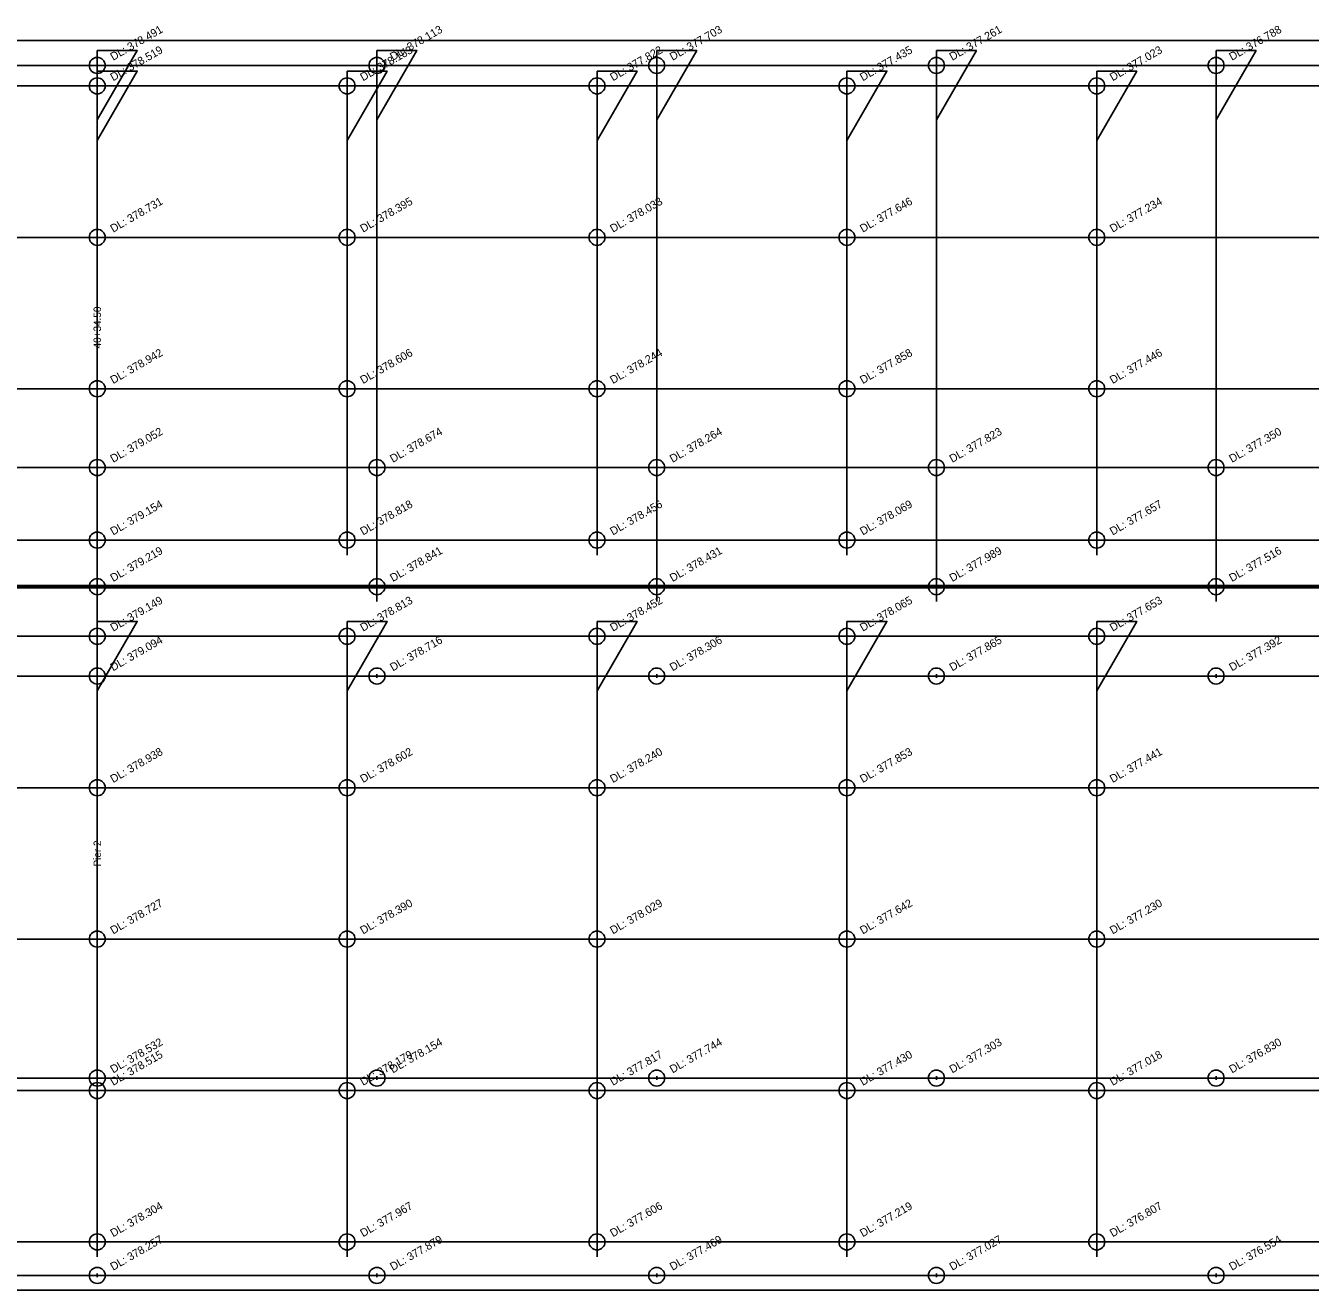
# Model space of a CAD drawing. Extents: x 100440 to 101111, y 50226 to 50315.
# Drawn here: x 100860.7 to 100946.9, y 50225.9 to 50310.8 of the extents above; entities that cross this region are included whole.
import ezdxf

# ---------------------------------------------------------------- set-up
doc = ezdxf.new("R2010")
doc.units = 0
for name, color, linetype in [('Level 1', 7, 'Continuous'), ('Level 10', 7, 'Continuous'), ('Level 21', 7, 'Continuous'), ('Level 23', 7, 'Continuous')]:
    doc.layers.add(name, color=color, linetype=linetype)

msp = doc.modelspace()

# ---------------------------------------------------------------- linework, layer by layer
at = {"layer": 'Level 1'}
for p, q in [((100559.504, 50306.768), (101034.504, 50306.768)), ((100559.504, 50296.601), (101034.504, 50296.601)), ((100865.504, 50288.143), (100865.504, 50258.143)), ((100865.504, 50288.143), (100865.504, 50258.143)), ((100559.504, 50286.435), (101034.504, 50286.435)), ((100559.504, 50276.268), (101034.504, 50276.268)), ((100559.504, 50269.81), (101034.504, 50269.81)), ((100559.504, 50259.643), (101034.504, 50259.643)), ((100559.504, 50249.476), (101034.504, 50249.476)), ((100559.504, 50239.31), (101034.504, 50239.31)), ((100559.504, 50229.143), (101034.504, 50229.143))]:
    msp.add_line(p, q, dxfattribs=at)
at = {"layer": 'Level 10'}
for p, q in [((100865.504, 50273.268), (100865.504, 50273.018)), ((100865.504, 50273.268), (100865.504, 50273.018)), ((100884.282, 50273.268), (100884.282, 50273.018)), ((100903.06, 50273.268), (100903.06, 50273.018)), ((100921.837, 50273.268), (100921.837, 50273.018)), ((100940.615, 50273.268), (100940.615, 50273.018)), ((100865.504, 50267.268), (100865.504, 50267.018)), ((100865.504, 50267.268), (100865.504, 50267.018)), ((100884.282, 50267.268), (100884.282, 50267.018)), ((100903.06, 50267.268), (100903.06, 50267.018)), ((100921.837, 50267.268), (100921.837, 50267.018)), ((100940.615, 50267.268), (100940.615, 50267.018)), ((100865.504, 50240.268), (100865.504, 50240.018)), ((100865.504, 50240.268), (100865.504, 50240.018)), ((100884.282, 50240.268), (100884.282, 50240.018)), ((100903.06, 50240.268), (100903.06, 50240.018)), ((100921.837, 50240.268), (100921.837, 50240.018)), ((100940.615, 50240.268), (100940.615, 50240.018)), ((100865.504, 50227.018), (100865.504, 50226.768)), ((100865.504, 50227.018), (100865.504, 50226.768)), ((100884.282, 50227.018), (100884.282, 50226.768)), ((100903.06, 50227.018), (100903.06, 50226.768)), ((100921.837, 50227.018), (100921.837, 50226.768)), ((100940.615, 50227.018), (100940.615, 50226.768))]:
    msp.add_line(p, q, dxfattribs=at)
for points in [[(100865.504, 50309.143), (100865.504, 50272.143)], [(100865.504, 50304.489), (100868.191, 50309.143), (100865.504, 50309.143)], [(100865.504, 50309.143), (100865.504, 50272.143)], [(100865.504, 50304.489), (100868.191, 50309.143), (100865.504, 50309.143)], [(100884.282, 50309.143), (100884.282, 50272.143)], [(100884.282, 50304.489), (100886.969, 50309.143), (100884.282, 50309.143)], [(100903.06, 50309.143), (100903.06, 50272.143)], [(100903.06, 50304.489), (100905.746, 50309.143), (100903.06, 50309.143)], [(100921.837, 50309.143), (100921.837, 50272.143)], [(100921.837, 50304.489), (100924.524, 50309.143), (100921.837, 50309.143)], [(100940.615, 50309.143), (100940.615, 50272.143)], [(100940.615, 50304.489), (100943.302, 50309.143), (100940.615, 50309.143)], [(100865.504, 50307.768), (100865.504, 50275.268)], [(100865.504, 50303.114), (100868.191, 50307.768), (100865.504, 50307.768)], [(100882.279, 50307.768), (100882.279, 50275.268)], [(100882.279, 50303.114), (100884.966, 50307.768), (100882.279, 50307.768)], [(100899.054, 50307.768), (100899.054, 50275.268)], [(100899.054, 50303.114), (100901.741, 50307.768), (100899.054, 50307.768)], [(100915.829, 50307.768), (100915.829, 50275.268)], [(100915.829, 50303.114), (100918.516, 50307.768), (100915.829, 50307.768)], [(100932.604, 50307.768), (100932.604, 50275.268)], [(100932.604, 50303.114), (100935.291, 50307.768), (100932.604, 50307.768)], [(100865.504, 50270.81), (100865.504, 50228.143)], [(100865.504, 50266.156), (100868.191, 50270.81), (100865.504, 50270.81)], [(100882.279, 50270.81), (100882.279, 50228.143)], [(100882.279, 50266.156), (100884.966, 50270.81), (100882.279, 50270.81)], [(100899.054, 50270.81), (100899.054, 50228.143)], [(100899.054, 50266.156), (100901.741, 50270.81), (100899.054, 50270.81)], [(100915.829, 50270.81), (100915.829, 50228.143)], [(100915.829, 50266.156), (100918.516, 50270.81), (100915.829, 50270.81)], [(100932.604, 50270.81), (100932.604, 50228.143)], [(100932.604, 50266.156), (100935.291, 50270.81), (100932.604, 50270.81)]]:
    msp.add_lwpolyline(points, dxfattribs=at)
for centre in [(100865.504, 50308.143), (100865.504, 50308.143), (100884.282, 50308.143), (100903.06, 50308.143), (100921.837, 50308.143), (100940.615, 50308.143), (100865.504, 50306.768), (100882.279, 50306.768), (100899.054, 50306.768), (100915.829, 50306.768), (100932.604, 50306.768), (100865.504, 50296.601), (100882.279, 50296.601), (100899.054, 50296.601), (100915.829, 50296.601), (100932.604, 50296.601), (100865.504, 50286.435), (100882.279, 50286.435), (100899.054, 50286.435), (100915.829, 50286.435), (100932.604, 50286.435), (100865.504, 50281.143), (100865.504, 50281.143), (100884.282, 50281.143), (100903.06, 50281.143), (100921.837, 50281.143), (100940.615, 50281.143), (100865.504, 50276.268), (100882.279, 50276.268), (100899.054, 50276.268), (100915.829, 50276.268), (100932.604, 50276.268), (100865.504, 50273.143), (100865.504, 50273.143), (100865.504, 50273.143), (100865.504, 50273.143), (100884.282, 50273.143), (100884.282, 50273.143), (100903.06, 50273.143), (100903.06, 50273.143), (100921.837, 50273.143), (100921.837, 50273.143), (100940.615, 50273.143), (100940.615, 50273.143), (100865.504, 50269.81), (100882.279, 50269.81), (100899.054, 50269.81), (100915.829, 50269.81), (100932.604, 50269.81), (100865.504, 50267.143), (100865.504, 50267.143), (100884.282, 50267.143), (100903.06, 50267.143), (100921.837, 50267.143), (100940.615, 50267.143), (100865.504, 50259.643), (100882.279, 50259.643), (100899.054, 50259.643), (100915.829, 50259.643), (100932.604, 50259.643), (100865.504, 50249.476), (100882.279, 50249.476), (100899.054, 50249.476), (100915.829, 50249.476), (100932.604, 50249.476), (100865.504, 50240.143), (100865.504, 50240.143), (100884.282, 50240.143), (100903.06, 50240.143), (100921.837, 50240.143), (100940.615, 50240.143), (100865.504, 50239.31), (100882.279, 50239.31), (100899.054, 50239.31), (100915.829, 50239.31), (100932.604, 50239.31), (100865.504, 50229.143), (100882.279, 50229.143), (100899.054, 50229.143), (100915.829, 50229.143), (100932.604, 50229.143), (100865.504, 50226.893), (100865.504, 50226.893), (100884.282, 50226.893), (100903.06, 50226.893), (100921.837, 50226.893), (100940.615, 50226.893)]:
    msp.add_circle(centre, 0.537, dxfattribs=at)
at = {"layer": 'Level 23'}
for p, q in [((100439.554, 50309.81), (101111.484, 50309.81)), ((100439.554, 50308.143), (101111.484, 50308.143)), ((100865.504, 50288.143), (100865.504, 50258.143)), ((100865.504, 50288.143), (100865.504, 50258.143)), ((100439.554, 50281.143), (101111.484, 50281.143)), ((100439.554, 50273.226), (101111.484, 50273.226)), ((100439.554, 50273.143), (101111.484, 50273.143)), ((100448.204, 50273.143), (101107.514, 50273.143)), ((100448.204, 50273.06), (101107.514, 50273.06)), ((100448.204, 50267.143), (101107.514, 50267.143)), ((100448.204, 50240.143), (101107.514, 50240.143)), ((100448.204, 50226.893), (101107.514, 50226.893)), ((100448.204, 50225.893), (101107.514, 50225.893))]:
    msp.add_line(p, q, dxfattribs=at)

# ---------------------------------------------------------------- texts
at = {"layer": 'Level 10'}
for s, p in [('DL: 378.491', (100866.569, 50308.448)), ('DL: 378.491', (100866.569, 50308.448)), ('DL: 378.113', (100885.347, 50308.448)), ('DL: 377.703', (100904.125, 50308.448)), ('DL: 377.261', (100922.902, 50308.448)), ('DL: 376.788', (100941.68, 50308.448)), ('DL: 378.519', (100866.569, 50307.073)), ('DL: 378.183', (100883.344, 50307.073)), ('DL: 377.822', (100900.119, 50307.073)), ('DL: 377.435', (100916.894, 50307.073)), ('DL: 377.023', (100933.669, 50307.073)), ('DL: 378.731', (100866.569, 50296.906)), ('DL: 378.395', (100883.344, 50296.906)), ('DL: 378.033', (100900.119, 50296.906)), ('DL: 377.646', (100916.894, 50296.906)), ('DL: 377.234', (100933.669, 50296.906)), ('DL: 378.942', (100866.569, 50286.739)), ('DL: 378.606', (100883.344, 50286.739)), ('DL: 378.244', (100900.119, 50286.739)), ('DL: 377.858', (100916.894, 50286.739)), ('DL: 377.446', (100933.669, 50286.739)), ('DL: 379.052', (100866.569, 50281.448)), ('DL: 379.052', (100866.569, 50281.448)), ('DL: 378.674', (100885.347, 50281.448)), ('DL: 378.264', (100904.125, 50281.448)), ('DL: 377.823', (100922.902, 50281.448)), ('DL: 377.350', (100941.68, 50281.448)), ('DL: 379.154', (100866.569, 50276.573)), ('DL: 378.818', (100883.344, 50276.573)), ('DL: 378.456', (100900.119, 50276.573)), ('DL: 378.069', (100916.894, 50276.573)), ('DL: 377.657', (100933.669, 50276.573)), ('DL: 379.219', (100866.569, 50273.448)), ('DL: 379.219', (100866.569, 50273.448)), ('DL: 379.219', (100866.569, 50273.448)), ('DL: 379.219', (100866.569, 50273.448)), ('DL: 378.841', (100885.347, 50273.448)), ('DL: 378.841', (100885.347, 50273.448)), ('DL: 378.431', (100904.125, 50273.448)), ('DL: 378.431', (100904.125, 50273.448)), ('DL: 377.989', (100922.902, 50273.448)), ('DL: 377.989', (100922.902, 50273.448)), ('DL: 377.516', (100941.68, 50273.448)), ('DL: 377.516', (100941.68, 50273.448)), ('DL: 379.149', (100866.569, 50270.114)), ('DL: 378.813', (100883.344, 50270.114)), ('DL: 378.452', (100900.119, 50270.114)), ('DL: 378.065', (100916.894, 50270.114)), ('DL: 377.653', (100933.669, 50270.114)), ('DL: 379.094', (100866.569, 50267.448)), ('DL: 379.094', (100866.569, 50267.448)), ('DL: 378.716', (100885.347, 50267.448)), ('DL: 378.306', (100904.125, 50267.448)), ('DL: 377.865', (100922.902, 50267.448)), ('DL: 377.392', (100941.68, 50267.448)), ('DL: 378.938', (100866.569, 50259.948)), ('DL: 378.602', (100883.344, 50259.948)), ('DL: 378.240', (100900.119, 50259.948)), ('DL: 377.853', (100916.894, 50259.948)), ('DL: 377.441', (100933.669, 50259.948)), ('DL: 378.727', (100866.569, 50249.781)), ('DL: 378.390', (100883.344, 50249.781)), ('DL: 378.029', (100900.119, 50249.781)), ('DL: 377.642', (100916.894, 50249.781)), ('DL: 377.230', (100933.669, 50249.781)), ('DL: 378.532', (100866.569, 50240.448)), ('DL: 378.532', (100866.569, 50240.448)), ('DL: 378.154', (100885.347, 50240.448)), ('DL: 377.744', (100904.125, 50240.448)), ('DL: 377.303', (100922.902, 50240.448)), ('DL: 376.830', (100941.68, 50240.448)), ('DL: 378.515', (100866.569, 50239.614)), ('DL: 378.179', (100883.344, 50239.614)), ('DL: 377.817', (100900.119, 50239.614)), ('DL: 377.430', (100916.894, 50239.614)), ('DL: 377.018', (100933.669, 50239.614)), ('DL: 378.304', (100866.569, 50229.448)), ('DL: 377.967', (100883.344, 50229.448)), ('DL: 377.606', (100900.119, 50229.448)), ('DL: 377.219', (100916.894, 50229.448)), ('DL: 376.807', (100933.669, 50229.448)), ('DL: 378.257', (100866.569, 50227.198)), ('DL: 378.257', (100866.569, 50227.198)), ('DL: 377.879', (100885.347, 50227.198)), ('DL: 377.469', (100904.125, 50227.198)), ('DL: 377.027', (100922.902, 50227.198)), ('DL: 376.554', (100941.68, 50227.198))]:
    msp.add_text(s, height=0.53732, rotation=30, dxfattribs=at).set_placement(p)
at = {"layer": 'Level 21'}
for s, p in [('40+34.50', (100865.754, 50289.143)), ('40+34.50', (100865.754, 50289.143)), ('Pier 2', (100865.754, 50254.351)), ('Pier 2', (100865.754, 50254.351))]:
    msp.add_text(s, height=0.5, rotation=90, dxfattribs=at).set_placement(p)

doc.saveas('drawing.dxf')
